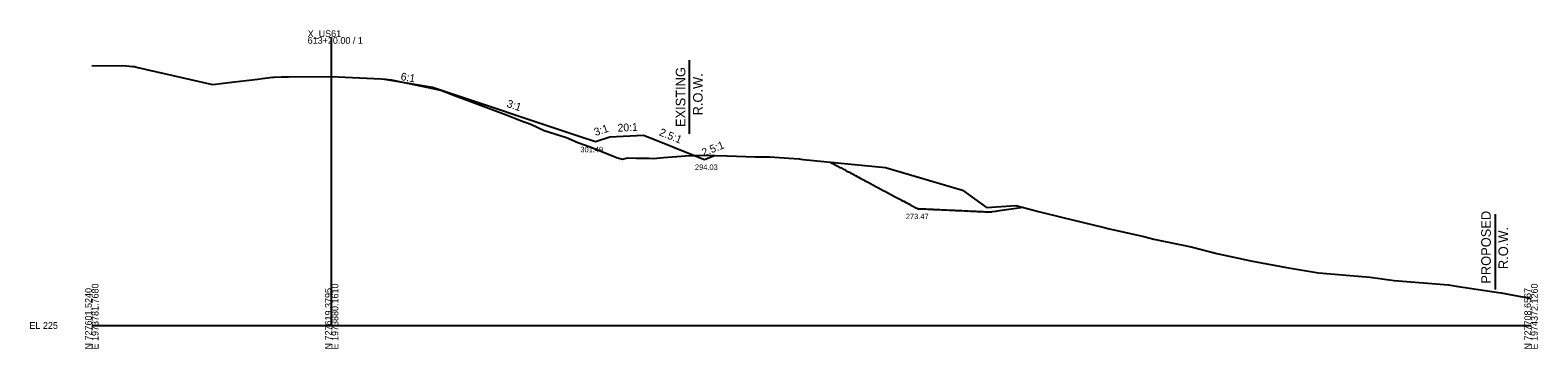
# Model space of a CAD drawing. Extents: x -26 to 1604, y -13 to 9623.
# Drawn here: x -26 to 603, y 2990 to 3123 of the extents above; entities that cross this region are included whole.
import ezdxf

# ---------------------------------------------------------------- set-up
doc = ezdxf.new("R2010")
doc.units = 0
for name, color, linetype in [('Draft_XS_Grid', 7, 'Continuous'), ('DTM CONTOURS_MAJOR', 7, 'Continuous'), ('DTM_X_GROUND', 7, 'Continuous'), ('SLOPE_STAKES_FILL', 7, 'Continuous'), ('XS_CELL', 7, 'Continuous'), ('XS_P_GROUND', 7, 'Continuous'), ('XS_P_ROW', 7, 'Continuous'), ('XS_P_TX_DCH', 7, 'Continuous'), ('XS_P_TX_FS_BS', 7, 'Continuous'), ('XS_X_ROW', 7, 'Continuous')]:
    doc.layers.add(name, color=color, linetype=linetype)

msp = doc.modelspace()

# ---------------------------------------------------------------- linework, layer by layer
at = {"layer": 'DTM_X_GROUND'}
msp.add_lwpolyline([(0, 3108.04), (12.93, 3108.2), (17.09, 3107.78), (17.74, 3107.72), (18.29, 3107.61), (19.16, 3107.36), (49.1, 3100.59), (50.47, 3100.31), (57.17, 3101.14), (69.25, 3102.54), (71.04, 3102.76), (71.07, 3102.76), (75.43, 3103.3), (76.1, 3103.25), (79.14, 3103.41), (79.51, 3103.45), (79.51, 3103.44), (82, 3103.46), (99.66, 3103.56), (120.61, 3102.61), (120.67, 3102.61), (120.69, 3102.61), (122.42, 3102.46), (124.87, 3102.25), (131.58, 3100.86), (145.52, 3097.89), (151.19, 3095.73), (156.48, 3093.72), (173.58, 3087.39), (178.79, 3085.32), (183.08, 3083.75), (188.6, 3081.06), (197.93, 3078.16), (202.63, 3076.15), (207.72, 3074.39), (217.07, 3070.54), (218.14, 3070.15), (218.76, 3069.95), (221.23, 3069.21), (221.78, 3069.33), (223.5, 3069.7), (227.06, 3069.66), (232.36, 3069.57), (234.15, 3069.54), (238.3, 3069.93), (247.53, 3070.56), (254.99, 3070.79), (264.83, 3070.59), (276.59, 3070.11), (280.41, 3070.15), (282.63, 3070.13), (290.54, 3069.55), (294.89, 3069.35), (295.56, 3069.25), (296.63, 3069.07), (330.82, 3065.79), (362.95, 3056.29), (372.97, 3049.1), (385.24, 3049.95), (390.45, 3048.51), (394.68, 3047.4), (404.82, 3044.9), (421.43, 3040.84), (422.67, 3040.59), (424.18, 3040.24), (426.75, 3039.67), (438.57, 3037.01), (442.82, 3035.93), (458.3, 3032.73), (468.99, 3029.98), (483.18, 3026.88), (498, 3024.13), (511.4, 3021.97), (532.95, 3020.14), (542.88, 3018.68), (565.58, 3016.91), (568.83, 3016.4), (586.42, 3013.78), (587.57, 3013.59), (600, 3011.22)], dxfattribs=at)
at = {"layer": 'XS_CELL'}
for p, q in [((100, 3000), (100, 3120)), ((0, 3000), (100, 3000)), ((100, 3000), (600, 3000))]:
    msp.add_line(p, q, dxfattribs=at)
at = {"layer": 'XS_P_GROUND'}
for points in [[(122, 3102.49), (142, 3099.16)], [(142, 3099.16), (204, 3078.49), (210, 3076.49), (216, 3078.49), (230, 3079.19), (235, 3077.19)], [(235, 3077.19), (249.41, 3071.43), (255.41, 3069.03)], [(255.41, 3069.03), (259.56, 3070.69)], [(307.75, 3068), (308.25, 3067.74), (308.3, 3067.71), (309.51, 3067.07), (309.67, 3066.98), (310.77, 3066.4), (311.03, 3066.26), (312.03, 3065.73), (312.38, 3065.54), (313.29, 3065.06), (313.73, 3064.83), (314.55, 3064.39), (315.07, 3064.11), (315.81, 3063.72), (316.4, 3063.4), (317.07, 3063.05), (317.73, 3062.7), (318.33, 3062.38), (319.05, 3061.99), (319.59, 3061.71), (320.37, 3061.29), (320.85, 3061.04), (321.69, 3060.59), (322.11, 3060.37), (323, 3059.89), (323.37, 3059.7), (324.31, 3059.2), (324.63, 3059.03), (325.62, 3058.5), (325.88, 3058.36), (326.92, 3057.81), (327.14, 3057.69), (328.22, 3057.12), (328.4, 3057.02), (329.52, 3056.43), (329.66, 3056.35), (330.82, 3055.74), (330.92, 3055.68), (332.12, 3055.05), (332.18, 3055.01), (333.41, 3054.36), (333.44, 3054.34), (334.61, 3053.72), (334.69, 3053.68), (334.7, 3053.67), (335.81, 3053.08), (335.96, 3053), (336.92, 3052.49), (337.22, 3052.33), (338.04, 3051.9), (338.48, 3051.66), (339.16, 3051.3), (339.74, 3050.99), (340.27, 3050.71), (341, 3050.32), (341.39, 3050.11), (342.26, 3049.65), (342.51, 3049.52), (343.52, 3048.98), (343.63, 3048.93), (344.48, 3048.47)], [(388.26, 3049.11), (377.48, 3047.57), (376.84, 3047.49), (375.35, 3047.24), (375.03, 3047.21), (374.45, 3047.11), (374.1, 3047.13), (373.74, 3047.14), (373.08, 3047.17), (372.48, 3047.2), (371.79, 3047.23), (371.22, 3047.26), (370.49, 3047.29), (369.96, 3047.32), (369.19, 3047.35), (368.71, 3047.37), (367.89, 3047.41), (367.45, 3047.43), (366.59, 3047.47), (366.19, 3047.49), (365.29, 3047.53), (364.93, 3047.55), (363.99, 3047.59), (363.67, 3047.6), (362.69, 3047.65), (362.41, 3047.66), (361.39, 3047.71), (361.15, 3047.72), (360.09, 3047.76), (359.89, 3047.77), (358.79, 3047.82), (358.63, 3047.83), (357.48, 3047.88), (357.37, 3047.89), (356.18, 3047.94), (356.11, 3047.95), (354.87, 3048), (354.85, 3048), (354.35, 3048.03), (353.59, 3048.06), (353.48, 3048.07), (352.33, 3048.12), (352.04, 3048.13), (351.07, 3048.17), (350.59, 3048.2), (349.81, 3048.23), (349.15, 3048.26), (348.55, 3048.29), (347.71, 3048.33), (347.29, 3048.35), (346.26, 3048.39), (346.04, 3048.4), (344.82, 3048.46), (344.78, 3048.46), (344.48, 3048.47)]]:
    msp.add_lwpolyline(points, dxfattribs=at)
at = {"layer": 'XS_P_ROW'}
msp.add_line((585, 3046.27), (585, 3015), dxfattribs=at)
at = {"layer": 'XS_X_ROW'}
msp.add_line((249, 3110.34), (249, 3079.8), dxfattribs=at)

# ---------------------------------------------------------------- texts
at = {"layer": 'Draft_XS_Grid'}
msp.add_text('-', height=0.0001, dxfattribs=at).set_placement((0, 3000))
at = {"layer": 'DTM CONTOURS_MAJOR'}
for p in [(334.57, 3053.66), (344.44, 3048.41), (344.44, 3048.41), (354.31, 3047.97), (378.2, 3047.62)]:
    msp.add_text('X', height=0.12, dxfattribs=at).set_placement(p)
at = {"layer": 'SLOPE_STAKES_FILL'}
for p in [(141.96, 3099.1), (203.96, 3078.43), (209.96, 3076.43), (215.96, 3078.43), (229.96, 3079.13), (249.37, 3071.37), (255.37, 3068.97), (259.52, 3070.63)]:
    msp.add_text('X', height=0.12, dxfattribs=at).set_placement(p)
at = {"layer": 'XS_CELL'}
for s, p in [('X_US61', (90, 3120)), ('613+20.00 / 1', (90, 3117.2)), ('EL 225', (-26, 2998.6))]:
    msp.add_text(s, height=2.8, dxfattribs=at).set_placement(p)
for s, p in [('E 1973781.7680', (2.8, 2990)), ('E 1973880.1610', (102.8, 2990)), ('E 1974372.1260', (602.8, 2990)), ('N 727601.5240', (0, 2990)), ('N 727619.3795', (100, 2990)), ('N 727708.6567', (600, 2990))]:
    msp.add_text(s, height=2.8, rotation=90, dxfattribs=at).set_placement(p)
at = {"layer": 'XS_P_GROUND'}
for p in [(121.96, 3102.43), (234.96, 3077.13)]:
    msp.add_text('X', height=0.12, dxfattribs=at).set_placement(p)
at = {"layer": 'XS_P_ROW'}
for s, p in [('PROPOSED', (583.23, 3017.38)), ('R.O.W.', (590.43, 3023.45))]:
    msp.add_text(s, height=4, rotation=90, dxfattribs=at).set_placement(p)
at = {"layer": 'XS_P_TX_DCH'}
for s, p in [('301.49', (203.68, 3072.08)), ('294.03', (251.46, 3064.73)), ('273.47', (339.36, 3044.26))]:
    msp.add_text(s, height=2.25, dxfattribs=at).set_placement(p)
at = {"layer": 'XS_P_TX_FS_BS'}
for s, rotation, p in [('6:1', 350.53766, (128.61, 3102.11)), ('3:1', 341.56507, (172.73, 3090.99)), ('3:1', 18.43493, (210, 3078.79)), ('20:1', 2.86241, (219.28, 3080.61)), ('2.5:1', 338.19859, (236.27, 3079.18)), ('2.5:1', 21.80141, (255.03, 3070.29))]:
    msp.add_text(s, height=3.24, rotation=rotation, dxfattribs=at).set_placement(p)
at = {"layer": 'XS_X_ROW'}
for s, p in [('EXISTING', (247.46, 3082.55)), ('R.O.W.', (254.66, 3087.4))]:
    msp.add_text(s, height=4, rotation=90, dxfattribs=at).set_placement(p)

doc.saveas('drawing.dxf')
